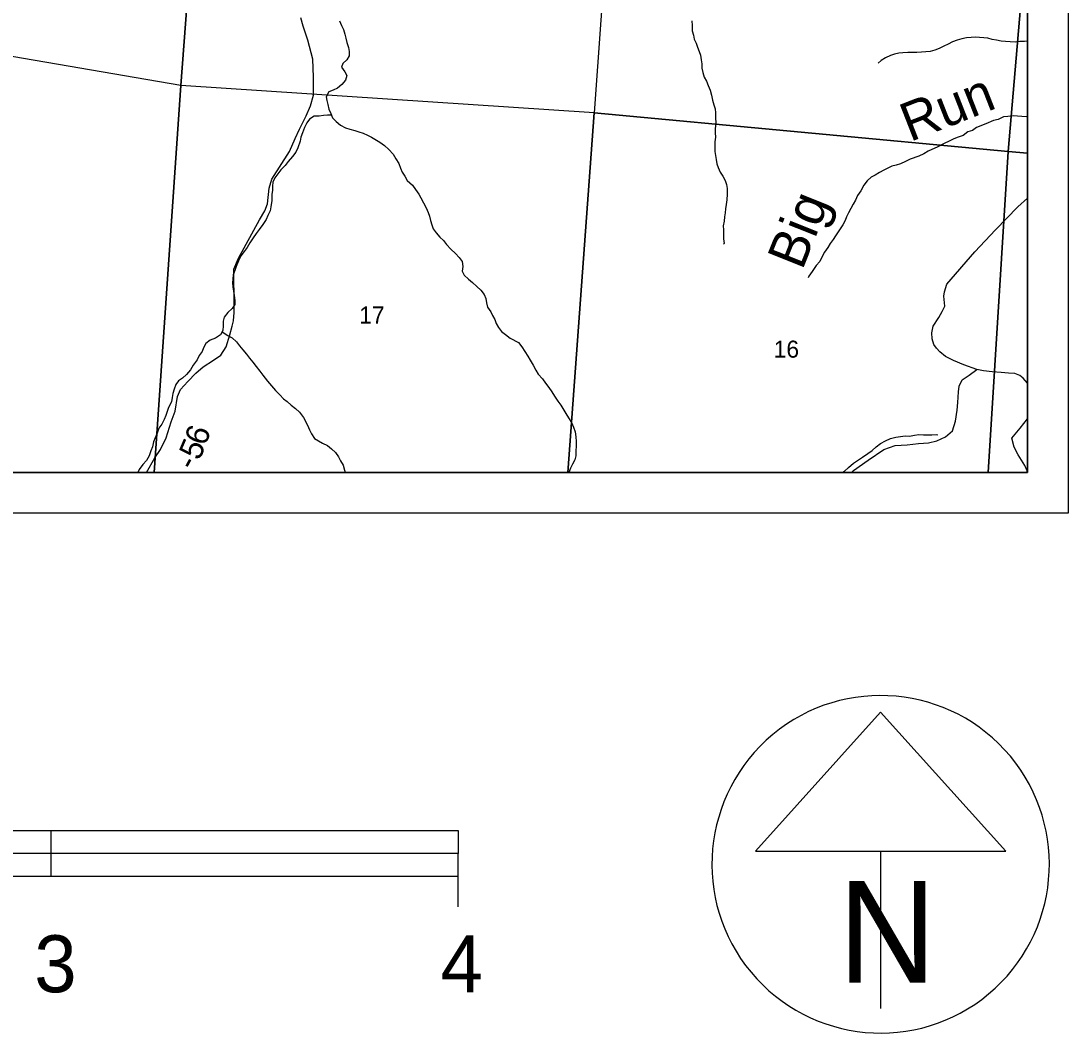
# Model space of a CAD drawing. Extents: x 0 to 34, y 0 to 22.
# Drawn here: x 28.342 to 30.917, y 12.722 to 15.21 of the extents above; entities that cross this region are included whole.
import ezdxf

# ---------------------------------------------------------------- set-up
doc = ezdxf.new("R2010")
doc.units = 0
for name, color, linetype in [('GM_X_County', 7, 'Continuous'), ('GM_X_County_Road', 7, 'Continuous'), ('GM_X_County_Road_Text', 7, 'Continuous'), ('GM_X_Minor_River', 7, 'Continuous'), ('GM_X_Minor_River_Text', 7, 'Continuous'), ('GM_X_Section', 7, 'Continuous'), ('GM_X_Section_Text', 7, 'Continuous'), ('GM_X_Township', 7, 'Continuous'), ('GM_X_Township_Road', 7, 'Continuous'), ('SH_Data', 7, 'Continuous'), ('SH_Text', 7, 'Continuous')]:
    doc.layers.add(name, color=color, linetype=linetype)

msp = doc.modelspace()

# ---------------------------------------------------------------- linework, layer by layer
at = {"layer": 'GM_X_County'}
msp.add_lwpolyline([(24.0167, 20.4902), (24.0167, 14.1), (30.8167, 14.1), (30.8167, 19.9966)], dxfattribs=at)
at = {"layer": 'GM_X_County_Road'}
msp.add_lwpolyline([(28.6503, 14.1), (28.6504, 14.1002), (28.671, 14.1358), (28.6851, 14.1566), (28.6988, 14.185), (28.7118, 14.2248), (28.721, 14.251), (28.7268, 14.2866), (28.7345, 14.3041), (28.7527, 14.3237), (28.7718, 14.3438), (28.7904, 14.36), (28.8155, 14.3759), (28.8337, 14.3887), (28.8467, 14.4092), (28.8559, 14.4384), (28.8616, 14.46), (28.8643, 14.4729), (28.8667, 14.4934), (28.8664, 14.5222), (28.8664, 14.5457), (28.8653, 14.564), (28.8654, 14.5803), (28.8655, 14.6), (28.8769, 14.6266), (28.9288, 14.7209), (28.9421, 14.7432), (28.9486, 14.7607), (28.9525, 14.799), (28.9591, 14.821), (29.0025, 14.8888), (29.0166, 14.921), (29.0266, 14.9441), (29.043, 14.9767), (29.0541, 15.0013), (29.0613, 15.0275), (29.0615, 15.0719), (29.0597, 15.1156), (29.0473, 15.1623), (29.036, 15.1969), (29.03, 15.2174)], dxfattribs=at)
at = {"layer": 'GM_X_Minor_River'}
for points in [[(29.1253, 15.2104), (29.1299, 15.1987), (29.1348, 15.1892), (29.1383, 15.1771), (29.1409, 15.1676), (29.1436, 15.157), (29.1474, 15.1448), (29.1489, 15.135), (29.149, 15.124), (29.1433, 15.1145), (29.1335, 15.1053), (29.1305, 15.0959), (29.1388, 15.0852), (29.1434, 15.0758), (29.14, 15.0644), (29.1313, 15.0537), (29.12, 15.045), (29.1098, 15.04), (29.0988, 15.0355), (29.0928, 15.0237), (29.0939, 15.0142), (29.0966, 15.0047), (29.0989, 14.993), (29.1042, 14.9827), (29.1077, 14.9717), (29.1175, 14.963), (29.1281, 14.9539), (29.1403, 14.9475), (29.1505, 14.9441), (29.1626, 14.9403), (29.1732, 14.9373), (29.1835, 14.9339), (29.1944, 14.929), (29.2039, 14.9241), (29.2248, 14.9116), (29.2358, 14.904), (29.2464, 14.8942), (29.2574, 14.8821), (29.2639, 14.8711), (29.2711, 14.8597), (29.2756, 14.8483), (29.2795, 14.8381), (29.2859, 14.8286), (29.2916, 14.8176)], [(29.992, 15.2103), (29.9924, 15.1985), (29.9928, 15.186), (29.9955, 15.1747), (29.997, 15.1652), (30.0019, 15.1549), (30.0054, 15.1455), (30.0099, 15.1352), (30.013, 15.1257), (30.0145, 15.1147), (30.0161, 15.1045), (30.0161, 15.0939), (30.0188, 15.0829), (30.0222, 15.0719), (30.0279, 15.0616), (30.0321, 15.051), (30.037, 15.0396), (30.0401, 15.0275), (30.0428, 15.0154), (30.0458, 15.004), (30.0492, 14.9938), (30.05, 14.9839), (30.05, 14.971), (30.0505, 14.96), (30.049, 14.9444), (30.0486, 14.9349), (30.0494, 14.9243), (30.0483, 14.9126), (30.0479, 14.9004), (30.048, 14.8886), (30.0499, 14.8788), (30.0518, 14.8693), (30.0533, 14.8591), (30.056, 14.8496)], [(30.8167, 15.1599), (30.8099, 15.1593), (30.7978, 15.1593), (30.7876, 15.1581), (30.7747, 15.1589), (30.763, 15.1596), (30.7524, 15.16), (30.741, 15.163), (30.73, 15.1641), (30.7194, 15.1675), (30.7092, 15.1682), (30.6993, 15.169), (30.6891, 15.1701), (30.6781, 15.1693), (30.6672, 15.1685), (30.6558, 15.1662), (30.6437, 15.1628), (30.6323, 15.1586), (30.6218, 15.1525), (30.6115, 15.1476), (30.5998, 15.1422), (30.5892, 15.1381), (30.5779, 15.135), (30.5673, 15.1338), (30.5563, 15.1334), (30.5446, 15.1327), (30.534, 15.1323), (30.5226, 15.1323), (30.5101, 15.1319), (30.5003, 15.1303), (30.49, 15.1284), (30.4802, 15.1246), (30.4681, 15.1193), (30.4575, 15.1124), (30.4496, 15.106)], [(29.1057, 14.978), (29.0955, 14.9782), (29.0857, 14.9774), (29.0751, 14.9759), (29.0633, 14.9762), (29.0512, 14.9686), (29.0448, 14.9591), (29.0392, 14.9481), (29.0347, 14.9352), (29.0305, 14.9242), (29.0286, 14.9147), (29.023, 14.898), (29.0181, 14.8874), (29.0098, 14.8771), (28.9988, 14.8642), (28.9913, 14.8547), (28.9811, 14.8437), (28.9739, 14.8342), (28.9667, 14.8239), (28.9615, 14.8137), (28.9607, 14.8042), (28.9604, 14.7939), (28.9589, 14.7833), (28.9589, 14.7685), (28.9567, 14.7533), (28.9552, 14.7435), (28.9491, 14.7317), (28.9446, 14.7218), (28.9371, 14.7097), (28.928, 14.6971), (28.9205, 14.6876), (28.9133, 14.677), (28.905, 14.6648), (28.8982, 14.6531), (28.891, 14.6432), (28.8831, 14.6329), (28.8767, 14.62), (28.8714, 14.6067), (28.8677, 14.5969), (28.8639, 14.5855), (28.8628, 14.576), (28.862, 14.5665), (28.8628, 14.5563), (28.8647, 14.546), (28.8667, 14.535), (28.8682, 14.5225), (28.8678, 14.5126), (28.8614, 14.5028), (28.8508, 14.4929), (28.8418, 14.4819), (28.8395, 14.4716), (28.8392, 14.4606), (28.8381, 14.4488), (28.8324, 14.4382), (28.8203, 14.4306), (28.8071, 14.4257), (28.7969, 14.4173), (28.7912, 14.4067), (28.7878, 14.3972), (28.7806, 14.3873), (28.775, 14.3767), (28.7659, 14.3637), (28.7588, 14.352), (28.7493, 14.3413), (28.7395, 14.3318), (28.7293, 14.3257), (28.7229, 14.3162), (28.7187, 14.3045), (28.7157, 14.2942), (28.7135, 14.2844), (28.712, 14.2741), (28.7048, 14.2601), (28.7014, 14.2498), (28.6984, 14.2399), (28.6943, 14.2301), (28.6886, 14.2191), (28.6807, 14.2088), (28.6766, 14.197), (28.672, 14.1849), (28.6679, 14.1754), (28.6653, 14.1629), (28.6615, 14.153), (28.6577, 14.1409), (28.6506, 14.1298), (28.6415, 14.1196), (28.6325, 14.1074), (28.6293, 14.1)], [(30.8167, 14.9753), (30.8137, 14.9745), (30.8031, 14.9753), (30.7921, 14.976), (30.7819, 14.9764), (30.7687, 14.9752), (30.7577, 14.974), (30.7452, 14.968), (30.7331, 14.9653), (30.7142, 14.9569), (30.6915, 14.9478), (30.6817, 14.9405), (30.6703, 14.9371), (30.6586, 14.9287), (30.6442, 14.9238), (30.634, 14.9192), (30.6242, 14.9146), (30.6124, 14.9089), (30.5966, 14.9006), (30.5731, 14.8899), (30.5621, 14.8834), (30.5497, 14.8773), (30.5281, 14.8701), (30.5171, 14.8648), (30.5043, 14.8587), (30.494, 14.8556), (30.4835, 14.8526), (30.4732, 14.848), (30.4634, 14.8434), (30.4532, 14.8377), (30.4422, 14.8312), (30.4324, 14.8259), (30.4226, 14.8172), (30.4143, 14.8065), (30.4071, 14.7921), (30.3992, 14.7807), (30.3939, 14.7697), (30.3879, 14.7598), (30.3822, 14.7488), (30.3769, 14.7382), (30.3716, 14.7287), (30.3686, 14.7192), (30.3626, 14.7086), (30.3513, 14.6915), (30.3445, 14.682), (30.3392, 14.6725), (30.3317, 14.6626), (30.3264, 14.6527), (30.3177, 14.6417), (30.3117, 14.6311), (30.3064, 14.6189), (30.2973, 14.6087)], [(30.056, 14.8496), (30.0613, 14.8382), (30.0678, 14.8287), (30.0735, 14.8177), (30.0769, 14.8083), (30.0788, 14.798), (30.0788, 14.784), (30.0777, 14.7703), (30.0763, 14.7589), (30.074, 14.7479), (30.0733, 14.7381), (30.0722, 14.7282), (30.071, 14.7179), (30.0688, 14.7066), (30.0692, 14.6967), (30.0696, 14.6846), (30.0692, 14.6743), (30.0708, 14.6629), (30.0693, 14.661)], [(29.2916, 14.8176), (29.3045, 14.8063), (29.3125, 14.796), (29.3205, 14.7843), (29.3254, 14.7748), (29.3322, 14.763), (29.3387, 14.7502), (29.3437, 14.7392), (29.3467, 14.7297), (29.349, 14.7194), (29.3524, 14.7088), (29.3559, 14.6993), (29.3631, 14.6887), (29.3718, 14.6785), (29.3813, 14.6705), (29.3885, 14.6603), (29.3991, 14.6489), (29.4105, 14.6383), (29.4196, 14.6285), (29.4268, 14.6186), (29.4288, 14.6061), (29.4273, 14.5951), (29.4322, 14.5853), (29.4428, 14.5754), (29.4527, 14.5671), (29.4633, 14.5572), (29.4732, 14.5478), (29.4812, 14.5375), (29.485, 14.5273), (29.4865, 14.5174), (29.4896, 14.5068), (29.4975, 14.4951), (29.5013, 14.4856), (29.507, 14.4761), (29.5105, 14.4659), (29.5162, 14.4564), (29.5238, 14.4462), (29.5332, 14.439), (29.5446, 14.4299), (29.5651, 14.4197), (29.5738, 14.4091), (29.5814, 14.3973), (29.5883, 14.3859), (29.5943, 14.3761), (29.6012, 14.3639), (29.6084, 14.3518), (29.6137, 14.342), (29.6247, 14.3302), (29.6319, 14.3196), (29.6403, 14.309), (29.6475, 14.2984), (29.654, 14.2878), (29.6623, 14.2753), (29.6695, 14.2654), (29.6817, 14.2449), (29.6882, 14.2343), (29.6961, 14.2226), (29.7003, 14.2116), (29.7049, 14.1998), (29.7064, 14.1877), (29.7072, 14.1759), (29.7072, 14.1649), (29.7065, 14.1535), (29.7062, 14.1414), (29.7039, 14.1315), (29.6982, 14.1205), (29.6933, 14.1107), (29.6892, 14.1)], [(30.2973, 14.6087), (30.2871, 14.5942), (30.2792, 14.5825), (30.2773, 14.5783)], [(28.8365, 14.446), (28.851, 14.4367), (28.8616, 14.4307), (28.8718, 14.4208), (28.8794, 14.4113), (28.8874, 14.4019), (28.8969, 14.3909), (28.9041, 14.3814), (28.9121, 14.3716), (28.9204, 14.3606), (28.9295, 14.3492), (28.9364, 14.3394), (28.9485, 14.3246), (28.9584, 14.3132), (28.9682, 14.3015), (28.9785, 14.2909), (28.9872, 14.2814), (28.9967, 14.2749), (29.0066, 14.2659), (29.0172, 14.2571), (29.0271, 14.2481), (29.0369, 14.2356), (29.0468, 14.2166), (29.0514, 14.2048), (29.0567, 14.1954), (29.0639, 14.1836), (29.0734, 14.1776), (29.0836, 14.1719), (29.0954, 14.1662), (29.106, 14.1586), (29.1155, 14.1492), (29.1231, 14.1386), (29.1276, 14.1287), (29.1345, 14.1177), (29.1375, 14.106), (29.1393, 14.1)], [(30.3643, 14.1), (30.3662, 14.1023), (30.3768, 14.1122), (30.3892, 14.1228), (30.3991, 14.1296), (30.4115, 14.138), (30.4244, 14.1468), (30.435, 14.154), (30.4448, 14.1631), (30.4554, 14.1711), (30.4679, 14.1779), (30.48, 14.1833), (30.4932, 14.1867), (30.505, 14.1883), (30.5163, 14.1898), (30.5265, 14.1894), (30.539, 14.1917), (30.5496, 14.1933), (30.5614, 14.1929), (30.572, 14.1925), (30.5818, 14.1926), (30.5928, 14.1933), (30.5966, 14.1926)]]:
    msp.add_lwpolyline(points, dxfattribs=at)
at = {"layer": 'GM_X_Section'}
for p, q in [((30.8167, 14.8848), (30.8167, 15.4443)), ((27.8688, 14.1), (28.67, 14.1)), ((28.67, 14.1), (29.6871, 14.1)), ((29.6871, 14.1), (30.7199, 14.1))]:
    msp.add_line(p, q, dxfattribs=at)
for points in [[(28.0441, 16.1595), (28.0465, 16.1852), (28.8121, 16.0697), (28.7351, 15.051), (27.9603, 15.1837)], [(28.8121, 16.0697), (29.8251, 16.0098), (29.7516, 14.9839), (28.7351, 15.051)]]:
    msp.add_lwpolyline(points, close=True, dxfattribs=at)
for points in [[(30.8167, 15.9231), (29.8251, 16.0098), (29.7516, 14.9839), (30.7695, 14.8891), (30.8167, 15.4443)], [(30.8167, 15.4443), (30.7695, 14.8891), (30.8167, 14.8848)], [(28.67, 14.1), (28.7351, 15.051), (27.9603, 15.1837), (27.9567, 15.147), (27.8688, 14.1)], [(29.6871, 14.1), (29.7516, 14.9839), (28.7351, 15.051), (28.67, 14.1)], [(30.7199, 14.1), (30.7695, 14.8891), (29.7516, 14.9839), (29.6871, 14.1)], [(30.8167, 14.8848), (30.7695, 14.8891), (30.7199, 14.1)], [(30.7199, 14.1), (30.8167, 14.1), (30.8167, 14.8848)]]:
    msp.add_lwpolyline(points, dxfattribs=at)
at = {"layer": 'GM_X_Township'}
msp.add_lwpolyline([(27.704, 14.1), (30.8167, 14.1), (30.8167, 19.9966)], dxfattribs=at)
at = {"layer": 'GM_X_Township_Road'}
for points in [[(30.8167, 14.3193), (30.806, 14.3322), (30.798, 14.3387), (30.7855, 14.3433), (30.7703, 14.3445), (30.7521, 14.3457), (30.7301, 14.3473), (30.7085, 14.3496), (30.6926, 14.3535), (30.6607, 14.365), (30.6346, 14.3753), (30.6153, 14.3853), (30.6016, 14.3963), (30.5929, 14.4058), (30.5869, 14.4146), (30.5824, 14.4283), (30.582, 14.4431), (30.5851, 14.4594), (30.5992, 14.481), (30.6072, 14.4957), (30.6137, 14.509), (30.6115, 14.5337), (30.6131, 14.5443), (30.6188, 14.5629), (30.6873, 14.642), (30.7383, 14.6968), (30.7935, 14.7532), (30.8167, 14.7746)], [(30.3842, 14.1), (30.3891, 14.1048), (30.4252, 14.1305), (30.464, 14.1569), (30.4913, 14.1667), (30.5213, 14.1681), (30.549, 14.1714), (30.5733, 14.1732), (30.5938, 14.1781), (30.6154, 14.1879), (30.6326, 14.2023), (30.6402, 14.2261), (30.6441, 14.2535), (30.6457, 14.2724), (30.6476, 14.2986), (30.6492, 14.3126), (30.6565, 14.3278), (30.6732, 14.3395), (30.6926, 14.3535)], [(30.8165, 14.1), (30.8159, 14.1041), (30.8103, 14.117), (30.7944, 14.1436), (30.7842, 14.1619), (30.7786, 14.1847), (30.7988, 14.2089), (30.8167, 14.2316)]]:
    msp.add_lwpolyline(points, dxfattribs=at)
at = {"layer": 'SH_Data'}
for p, q in [((30.4559, 13.5108), (30.1483, 13.1696)), ((30.7635, 13.1696), (30.4559, 13.5108)), ((27.4167, 13.22), (28.4167, 13.22)), ((28.4167, 13.1638), (28.4167, 13.22)), ((28.4167, 13.22), (29.4167, 13.22)), ((29.4167, 13.22), (29.4167, 13.1638)), ((28.4167, 13.1638), (27.4167, 13.1638)), ((28.4167, 13.1075), (28.4167, 13.1638)), ((29.4167, 13.1638), (28.4167, 13.1638)), ((29.4167, 13.0325), (29.4167, 13.1638)), ((30.1483, 13.1696), (30.7635, 13.1696)), ((30.4559, 13.1696), (30.4559, 12.7828)), ((27.4167, 13.1075), (28.4167, 13.1075)), ((28.4167, 13.1075), (29.4167, 13.1075))]:
    msp.add_line(p, q, dxfattribs=at)
for points in [[(23.9167, 21), (30.9167, 21), (30.9167, 14), (23.9167, 14)], [(24.0167, 20.9), (30.8167, 20.9), (30.8167, 14.1), (24.0167, 14.1)]]:
    msp.add_lwpolyline(points, close=True, dxfattribs=at)
msp.add_arc((30.4559, 13.1371), 0.4148, 129.7798, 129.7633, dxfattribs=at)

# ---------------------------------------------------------------- texts
at = {"layer": 'GM_X_County_Road_Text'}
for s, rotation, p in [('6', 70.3666, (28.7959, 14.1634)), ('5', 66.6414, (28.7806, 14.1276)), ('-', 61.3605, (28.7669, 14.1019))]:
    msp.add_text(s, height=0.0568, rotation=rotation, dxfattribs=at).set_placement(p)
at = {"layer": 'GM_X_Minor_River_Text'}
for s, rotation, p in [('Run', 21.3698, (30.528, 14.912)), ('Big', 68.2341, (30.2629, 14.5951))]:
    msp.add_text(s, height=0.0947, rotation=rotation, dxfattribs=at).set_placement(p)
at = {"layer": 'GM_X_Section_Text'}
for s, p in [('17', (29.1739, 14.4662)), ('16', (30.193, 14.3823))]:
    msp.add_text(s, height=0.04186, rotation=0, dxfattribs=at).set_placement(p)
at = {"layer": 'SH_Data'}
msp.add_text('N', height=0.25, rotation=360, dxfattribs=at).set_placement((30.3518, 12.8457))
at = {"layer": 'SH_Text'}
for s, p in [('3', (28.3748, 12.8225)), ('4', (29.3739, 12.8225))]:
    msp.add_text(s, height=0.14, dxfattribs=at).set_placement(p)

doc.saveas('drawing.dxf')
